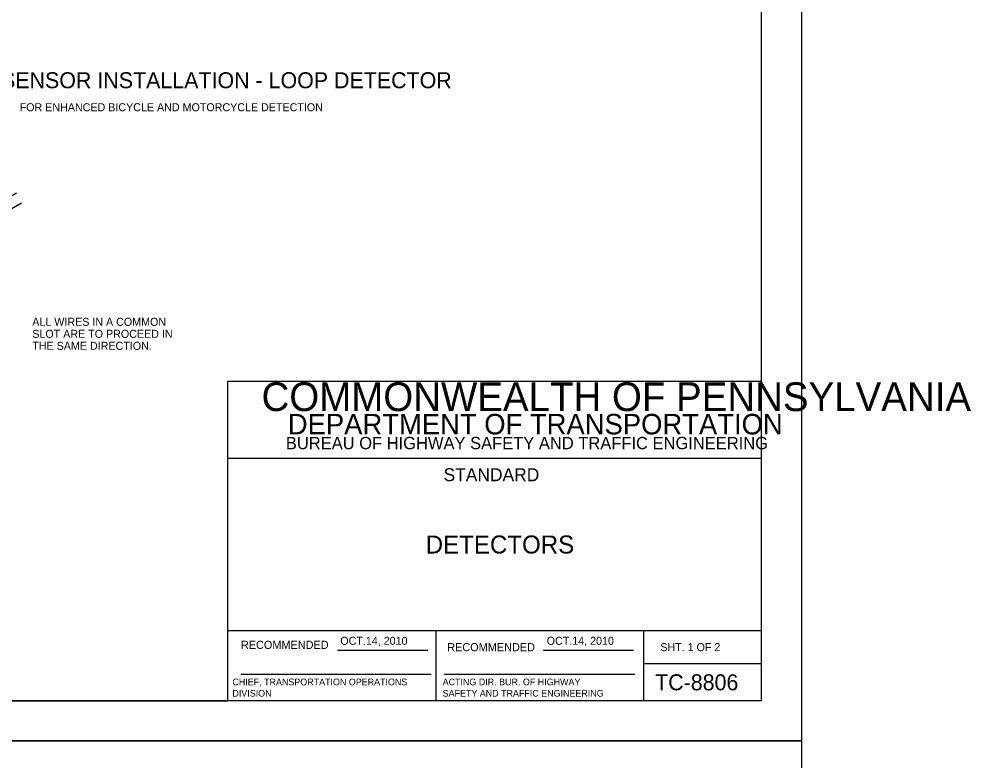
# Model space of a CAD drawing. Extents: x 2709 to 3899, y 22 to 1210.
# Drawn here: x 3256.6 to 3613.4, y 608.7 to 886.9 of the extents above; entities that cross this region are included whole.
import ezdxf

# ---------------------------------------------------------------- set-up
doc = ezdxf.new("R2010")
doc.units = 0
for name, color, linetype in [('1', 7, 'Continuous'), ('17', 7, 'Continuous'), ('2', 7, 'Continuous'), ('4', 7, 'Continuous'), ('Default', 7, 'Continuous'), ('PLT-BNDY', 7, 'Continuous')]:
    doc.layers.add(name, color=color, linetype=linetype)

msp = doc.modelspace()

# ---------------------------------------------------------------- linework, layer by layer
at = {"layer": '1'}
for p, q in [((3534.86, 631.17), (3534.86, 1195.17)), ((3334.86, 631.17), (3334.86, 751.17)), ((3334.86, 751.17), (3534.86, 751.17)), ((3534.86, 722.17), (3334.86, 722.17)), ((3334.86, 657.55), (3534.86, 657.55)), ((3412.86, 657.55), (3412.86, 631.17)), ((3490.73, 631.17), (3490.73, 657.55)), ((3375.9, 650.2), (3409.82, 650.2)), ((3452.99, 650.2), (3486.91, 650.2)), ((3490.73, 645.17), (3534.86, 645.17)), ((3339.74, 641.21), (3411.07, 641.21)), ((3415.95, 641.21), (3487.41, 641.21)), ((3534.86, 631.17), (2748.86, 631.17)), ((2748.86, 631.17), (3334.86, 631.17))]:
    msp.add_line(p, q, dxfattribs=at)
at = {"layer": '2'}
msp.add_lwpolyline([(3255.55, 821.67), (3244.8, 815.42), (3235.05, 825.17), (3223.42, 813.67), (3223.42, 721.17), (3208.67, 706.42), (3194.8, 720.17), (3194.8, 812.67), (3206.42, 824.3), (3217.92, 812.67), (3217.92, 720.17), (3232.67, 705.42), (3246.55, 719.3), (3246.55, 811.8), (3257.42, 818.05)], dxfattribs=at)
at = {"layer": 'PLT-BNDY'}
for points in [[(2708.86, 1210.17), (3549.86, 1210.17), (3549.86, 616.17), (2708.86, 616.17)], [(2708.86, 616.17), (3549.86, 616.17), (3549.86, 22.17), (2708.86, 22.17)]]:
    msp.add_lwpolyline(points, close=True, dxfattribs=at)

# ---------------------------------------------------------------- texts
at = {"layer": '1'}
for s, height, p in [('COMMONWEALTH OF PENNSYLVANIA', 10.7828, (3347.45, 739.9)), ('DEPARTMENT OF TRANSPORTATION', 7.6837, (3357.31, 731.15)), ('BUREAU OF HIGHWAY SAFETY AND TRAFFIC ENGINEERING', 4.6253, (3356.58, 725.59)), ('DETECTORS', 6.75, (3409.01, 686.48)), ('RECOMMENDED', 3.0516, (3339.73, 650.7)), ('OCT.14, 2010', 3, (3376.98, 652.24)), ('RECOMMENDED', 3.0516, (3417.08, 649.82)), ('SHT. 1 OF 2', 3, (3496.94, 649.86)), ('TC-8806', 6, (3495, 635.17))]:
    msp.add_text(s, height=height, dxfattribs=at).set_placement(p)
msp.add_text('OCT.14, 2010', height=3, rotation=360, dxfattribs=at).set_placement((3454.36, 652.24))
at = {"layer": '17'}
msp.add_text('FOR ENHANCED BICYCLE AND MOTORCYCLE DETECTION', height=3, dxfattribs=at).set_placement((3256.79, 852.35))
at = {"layer": '2'}
for s, height, p in [('ALTERNATE SENSOR INSTALLATION - LOOP DETECTOR', 6, (3200.31, 860.98)), ('ALL WIRES IN A COMMON', 3, (3261.52, 771.87)), ('SLOT ARE TO PROCEED IN', 3, (3261.52, 767.37)), ('THE SAME DIRECTION.', 3, (3261.52, 762.87))]:
    msp.add_text(s, height=height, dxfattribs=at).set_placement(p)
at = {"layer": '4'}
msp.add_text('STANDARD', height=4.881, rotation=360, dxfattribs=at).set_placement((3415.69, 713.59))
at = {"layer": 'Default'}
for s, p in [('CHIEF, TRANSPORTATION OPERATIONS', (3336.54, 637.06)), ('ACTING DIR. BUR. OF HIGHWAY', (3415.35, 637.06)), ('DIVISION', (3336.54, 632.81)), ('SAFETY AND TRAFFIC ENGINEERING', (3415.35, 632.81))]:
    msp.add_text(s, height=2.5, dxfattribs=at).set_placement(p)

doc.saveas('drawing.dxf')
